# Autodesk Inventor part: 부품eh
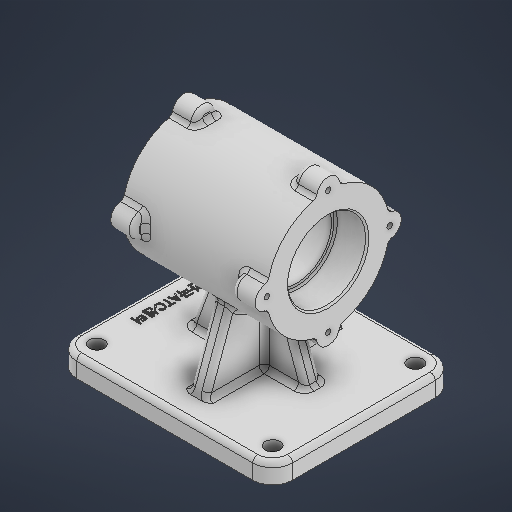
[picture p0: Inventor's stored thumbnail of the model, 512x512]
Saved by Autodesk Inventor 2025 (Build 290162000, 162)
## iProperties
Created: 2025-08
Part Number: 부품eh
Material: 일반
Document SubType Name: Modeling
Designer: infra006
Density: 1 g/cm^3
Appearance: 기본값
Author: infra006
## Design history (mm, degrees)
sketch "스케치1"
  geometry: L1 (-43.5, 0)-(43.5, 0); L2 (43.5, 0)-(43.5, 23.5); L3 (43.5, 23.5)-(-43.5, 23.5); L4 (-43.5, 23.5)-(-43.5, 0); L5 (-43.5, 0)-(-24.5, 0); L6 (-24.5, 0)-(-24.5, 23.5); L7 (-24.5, 23.5)-(-43.5, 23.5); L8 (-43.5, 23.5)-(-43.5, 0); L9 (43.5, 0)-(24.5, 0); L10 (24.5, 0)-(24.5, 23.5); L11 (24.5, 23.5)-(43.5, 23.5); L12 (43.5, 23.5)-(43.5, 0); L13 (24.5, 0)-(-24.5, 0); L14 (-24.5, 0)-(-24.5, 21); L15 (-24.5, 21)-(24.5, 21); L16 (24.5, 21)-(24.5, 0); L17 (-43.5, 0)-(43.5, 0); L18 (43.5, 0)-(43.5, 37); L19 (43.5, 37)-(-43.5, 37); L20 (-43.5, 37)-(-43.5, 0); 6 further points
  constraints: 40 end point, 10 parallel, 5 horizontal, 5 perpendicular, 2 point on line, 1 coincident, 1 midpoint
  dimensions: "d1" = 87 distance of L3.end L2.end; "d2" = 19 distance of L7.end L6.end; "d3" = 23.5 distance of L6.end L5.end; "d4" = 23.5 distance of L1.end L2.end; "d5" = 19 distance of L10.end L11.end; "d6" = 21 distance of L13.end L14.end; "d7" = 37 distance of L18.end L17.end; "d8" = 87 distance between parallel lines of L20 L18
revolve "회전1" sketch "스케치1" stored, may be unused: angle "d9" = 90 deg
sketch "스케치2"
  geometry: L1 (0, 0)-(0, -82); L2 (0, -82)-(65, -82); L3 (0, -82)-(-65, -82); L4 (-65, -82)-(-65, -70); L5 (-65, -70)-(65, -70); L6 (65, -70)-(65, -82)
  constraints: 12 end point, 2 horizontal, 2 perpendicular, 2 vertical
  dimensions: "d10" = 82 distance of L1.start L1.end; "d11" = 65 distance of L1.end L2.end; "d12" = 65 distance of L1.end L3.end; "d13" = 12 distance of L3.end L4.end
extrude "돌출1" join sketch "스케치2" stored distance "d14" = 110; taper "d15" = 0 deg
sketch "스케치3"
  geometry: L1 (0, 0)-(0, 110) reference; L2 (0, 0)-(130, 0) reference; L3 (130, 110)-(0, 110) reference; L4 (12, 98)-(118, 98); L5 (118, 98)-(118, 12); L6 (118, 12)-(12, 12); L7 (12, 12)-(12, 98)
  constraints: 8 end point, 2 parallel, 1 horizontal, 1 perpendicular
  dimensions: "d20" = 106 distance between parallel lines of L5 L7; "d21" = 86 distance between parallel lines of L6 L4; "d22" = 12 distance between parallel lines of L1 L7; "d23" = 12 distance between parallel lines of L3 L4
hole "구멍1" sketch "스케치3" at (12, 98), (12, 12), (118, 12), (118, 98) diameter "d24" = 9; stored, may be unused: countersink angle "d28" = 90 deg, drill point angle "d30" = 118 deg; dims "d25" = 6, "d26" = 4, "d27" = 2, "d29" = 12
sketch "스케치4"
  geometry: L1 (60, 50)-(70, 50); L2 (70, 50)-(70, 60); L3 (70, 60)-(60, 60); L4 (60, 60)-(60, 50); L5 (60, 50)-(70, 60); L6 (70, 50)-(60, 60); 1 further point
  constraints: 12 end point, 2 midpoint, 2 parallel, 1 horizontal, 1 perpendicular
  dimensions: "d31" = 10 distance of L3.end L2.end; "d32" = 10 distance of L2.end L1.end
extrude "돌출2" join sketch "스케치4" stored distance "d33" = 110; taper "d34" = 0 deg
sketch "스케치5"
  geometry: L1 (-5, -70)-(-5, -36.661) reference; L2 (-5, -70)-(-35, -70); L3 (-65, -70)-(65, -70) reference; L4 (-35, -70)-(-22.989, -37); L5 (43.5, -37)-(-43.5, -37) reference; L6 (5, -70)-(5, -36.661) reference; L7 (5, -70)-(35, -70); L8 (35, -70)-(22.989, -37); 1 further point
  constraints: 8 end point, 4 point on line
  dimensions: "d35" = 30 distance of L1.start L2.end; "d36" = 70 deg angle of L2 L4; "d37" = 30 distance of L6.start L7.end; "d38" = 70 deg angle of L8 L7
feature "리브1" dims "d39" = 1, "d40" = 10, "d41" = 0, "d42" = 0, "d43" = 1, "d44" = 1
feature "리브2" dims "d45" = 1, "d46" = 10, "d47" = 0, "d48" = 0, "d49" = 1, "d50" = 1
sketch "스케치7"
  geometry: C1 r 7 at (0, 37); C2 r 7 at (-37, 0); C3 r 7 at (0, -37); C4 r 7 at (37, 0); 10 further points
  constraints: 4 centre point, 1 horizontal alignment, 11 other
  dimensions: "d64" = 14 diameter of C1; "d67" = 360 deg dimension on point (0, 0) C1.centre (derived); "d69" = 37 distance of point (0, 0) C1.centre (derived); "d70" = 14 diameter of C2 (derived); "d71" = 37 distance of point (0, 0) C2.centre (derived)
extrude "돌출3" join sketch "스케치7" distance "d72" = 14; taper "d73" = 0 deg
sketch "스케치9"
  geometry: A1 r 37 centre (37, 0) between (0, 0) and (37, 37); 4 further points
  constraints: 4 point on circle, 2 coincident, 1 centre point
  dimensions: "d74" = 74 diameter of A1
hole "구멍3" sketch "스케치9" at (0, 0), (37, 37), (74, 0), (37, -37) diameter "d82" = 3.242; stored, may be unused: countersink angle "d86" = 90 deg, drill point angle "d88" = 118 deg; dims "d83" = 8, "d84" = 4, "d85" = 2, "d87" = 10
chamfer "모따기1" distance "d89" = 1; stored, may be unused: second distance "d90" = 2, angle "d91" = 45 deg
chamfer "모따기2" distance "d92" = 1; stored, may be unused: second distance "d93" = 2, angle "d94" = 45 deg
fillet "모깎기1" dims "d95" = 1
fillet "모깎기2" dims "d96" = 12
fillet "모깎기3" dims "d97" = 3
fillet "모깎기4" dims "d98" = 3
fillet "모깎기6" dims "d100" = 3
fillet "모깎기7" dims "d101" = 3
sketch "스케치10"
  geometry: L1 (2.821, -29.814)-(2.821, -74.186); L2 (2.821, -74.186)-(-2.821, -74.186); L3 (-2.821, -74.186)-(-2.821, -29.814); L4 (-2.821, -29.814)-(2.821, -29.814); L5 (0, -29.814)-(0, -74.186); L6 (2.821, -52)-(-2.821, -52); L7 (-12, -9)-(-12, -95) reference; L8 (118, -95)-(118, -9) reference; 4 further points
  constraints: 7 midpoint, 4 end point, 1 horizontal alignment, 1 vertical alignment, 2 other
  dimensions: "d103" = 44.37127 distance between parallel lines of L2 L4; "d116" = 118 distance from line of L5 point (118, -52); "d117" = 5.64185 distance between parallel lines of L3 L1
node "작업 평면1"
sketch "스케치12"
  geometry: L1 (-70, -55)-(-70, -41); L2 (-70, -43)-(-70, -52) reference; L3 (-70, -41)-(-26.964, -25.336); A1 r 37 centre (0, 0) between (-35.863, -9.104) and (-9.104, -35.863) reference; 1 further point
  constraints: 4 end point, 1 collinear, 1 point on circle
  dimensions: "d107" = 14 distance of L1.start L1.end; "d108" = 110 deg angle of L1 L3
feature "리브4" sketch "스케치12" dims "d109" = 1, "d110" = 10, "d111" = 0, "d112" = 0, "d113" = 1, "d114" = 1
feature "엠보싱1" dims "d1" = 87, "d2" = 19, "d3" = 23.5, "d4" = 23.5, "d5" = 19, "d6" = 21, "d7" = 37, "d8" = 87, "d118" = 0.5, "d119" = 0
fillet "모깎기10" dims "d122" = 3
node "솔리드1"
mirror "미러2"
mirror "미러3"
mirror "미러4"
mirror "미러5"
node "스케치 - 원형 패턴1" dims "d67" = 360 deg (derived)
feature "A9D066F2-1C7D-4E18-AEED-F7BC21143FA4" dims "d24" = 9, "d25" = 6, "d26" = 4, "d27" = 2, "d28" = 90 deg, "d29" = 12, "d30" = 118 deg
other parameters: "d106" = 5
